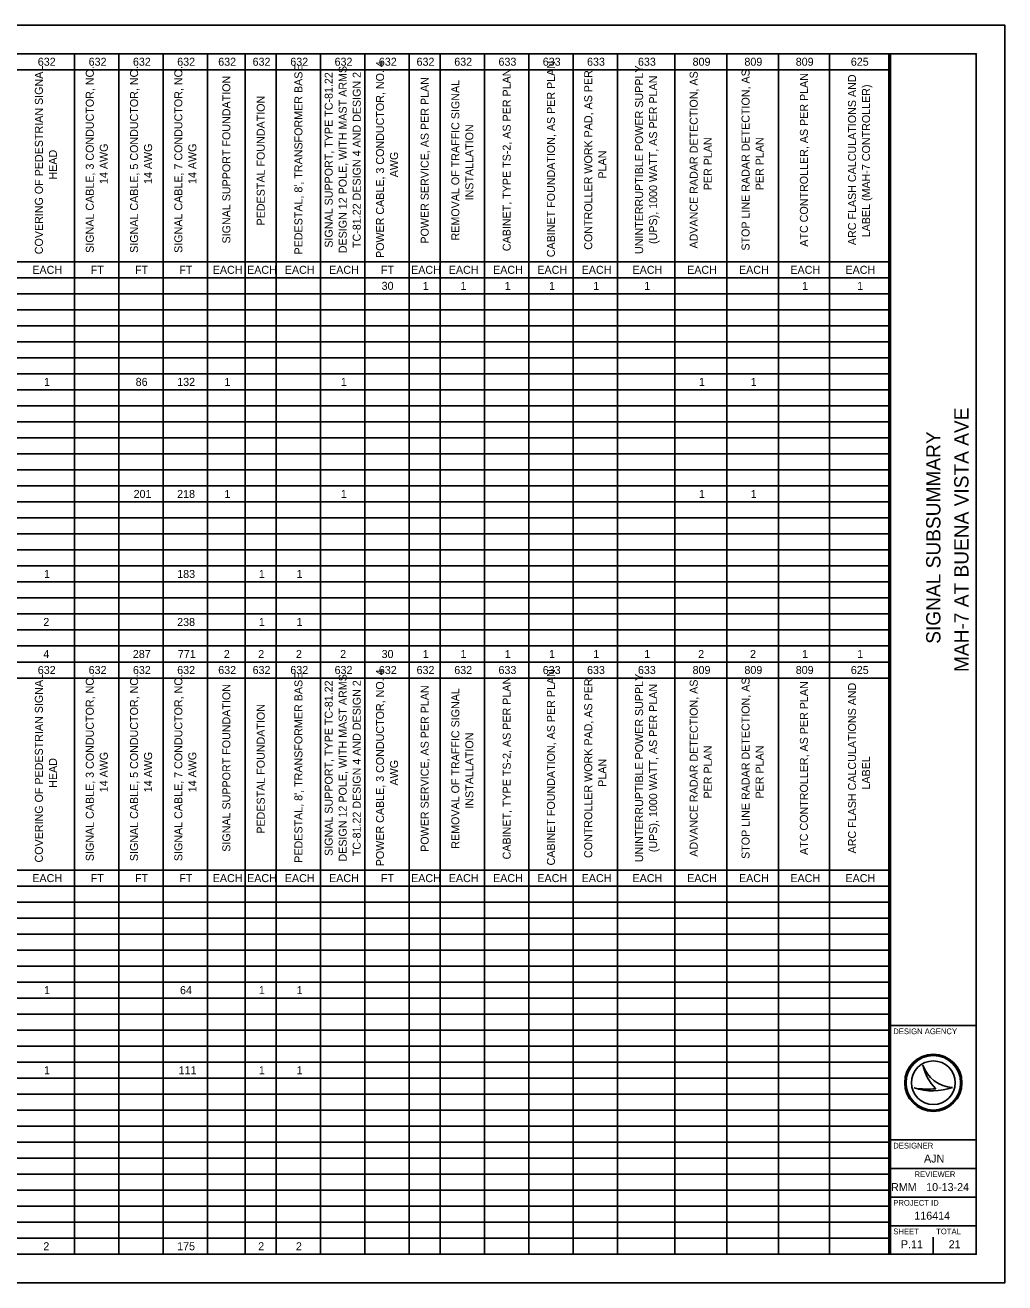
# Model space of a CAD drawing. Extents: x 0 to 34, y 0 to 22.
# Drawn here: x 16.88 to 34, y 0 to 22 of the extents above; entities that cross this region are included whole.
import ezdxf

# ---------------------------------------------------------------- set-up
doc = ezdxf.new("R2010")
doc.units = 0
for name, color, linetype in [('Default', 7, 'Continuous'), ('SH_Border', 7, 'Continuous'), ('SH_Cut_Line', 7, 'Continuous'), ('SH_Data', 7, 'Continuous'), ('SH_Text', 7, 'Continuous')]:
    doc.layers.add(name, color=color, linetype=linetype)

msp = doc.modelspace()

# ---------------------------------------------------------------- linework, layer by layer
at = {"layer": 'Default'}
for p, q in [((1.5, 21.5), (31.971, 21.5)), ((17.74, 21.5), (17.74, 10.86)), ((18.514, 21.5), (18.514, 10.86)), ((19.288, 21.5), (19.288, 10.86)), ((20.062, 21.5), (20.062, 10.86)), ((20.721, 21.5), (20.721, 10.86)), ((21.265, 21.5), (21.265, 10.86)), ((22.039, 21.5), (22.039, 10.86)), ((22.813, 21.5), (22.813, 10.86)), ((23.587, 21.5), (23.587, 10.86)), ((24.131, 21.5), (24.131, 10.86)), ((24.905, 21.5), (24.905, 10.86)), ((25.679, 21.5), (25.679, 10.86)), ((26.453, 21.5), (26.453, 10.86)), ((27.227, 21.5), (27.227, 10.86)), ((28.232, 21.5), (28.232, 10.86)), ((29.138, 21.5), (29.138, 10.86)), ((30.044, 21.5), (30.044, 10.86)), ((30.933, 21.5), (30.933, 10.86)), ((31.971, 21.5), (31.971, 10.86)), ((8.484, 21.22), (31.971, 21.22)), ((8.484, 17.86), (31.971, 17.86)), ((1.5, 17.58), (31.971, 17.58)), ((1.5, 17.3), (31.971, 17.3)), ((1.5, 17.02), (31.971, 17.02)), ((1.5, 16.74), (31.971, 16.74)), ((1.5, 16.46), (31.971, 16.46)), ((1.5, 16.18), (31.971, 16.18)), ((1.5, 15.9), (31.971, 15.9)), ((1.5, 15.62), (31.971, 15.62)), ((1.5, 15.34), (31.971, 15.34)), ((1.5, 15.06), (31.971, 15.06)), ((1.5, 14.78), (31.971, 14.78)), ((1.5, 14.5), (31.971, 14.5)), ((1.5, 14.22), (31.971, 14.22)), ((1.5, 13.94), (31.971, 13.94)), ((1.5, 13.66), (31.971, 13.66)), ((1.5, 13.38), (31.971, 13.38)), ((1.5, 13.1), (31.971, 13.1)), ((1.5, 12.82), (31.971, 12.82)), ((1.5, 12.54), (31.971, 12.54)), ((1.5, 12.26), (31.971, 12.26)), ((1.5, 11.98), (31.971, 11.98)), ((1.5, 11.7), (31.971, 11.7)), ((1.5, 11.42), (31.971, 11.42)), ((1.5, 11.14), (31.971, 11.14)), ((1.5, 10.86), (32.004, 10.86)), ((1.5, 10.86), (31.971, 10.86)), ((1.5, 10.86), (31.971, 10.86)), ((17.74, 10.86), (17.74, 0.5)), ((18.514, 10.86), (18.514, 0.5)), ((19.288, 10.86), (19.288, 0.5)), ((20.062, 10.86), (20.062, 0.5)), ((20.721, 10.86), (20.721, 0.5)), ((21.265, 10.86), (21.265, 0.5)), ((22.039, 10.86), (22.039, 0.5)), ((22.813, 10.86), (22.813, 0.5)), ((23.587, 10.86), (23.587, 0.5)), ((24.131, 10.86), (24.131, 0.5)), ((24.905, 10.86), (24.905, 0.5)), ((25.679, 10.86), (25.679, 0.5)), ((26.453, 10.86), (26.453, 0.5)), ((27.227, 10.86), (27.227, 0.5)), ((28.232, 10.86), (28.232, 0.5)), ((29.138, 10.86), (29.138, 0.5)), ((30.044, 10.86), (30.044, 0.5)), ((30.933, 10.86), (30.933, 0.5)), ((31.971, 10.86), (31.971, 0.5)), ((8.484, 10.58), (31.971, 10.58)), ((8.484, 7.22), (31.971, 7.22)), ((1.5, 6.94), (31.971, 6.94)), ((1.5, 6.66), (31.971, 6.66)), ((1.5, 6.38), (31.971, 6.38)), ((1.5, 6.1), (31.971, 6.1)), ((1.5, 5.82), (31.971, 5.82)), ((1.5, 5.54), (31.971, 5.54)), ((1.5, 5.26), (31.971, 5.26)), ((1.5, 4.98), (31.971, 4.98)), ((1.5, 4.7), (31.971, 4.7)), ((1.5, 4.42), (31.971, 4.42)), ((1.5, 4.14), (31.971, 4.14)), ((1.5, 3.86), (31.971, 3.86)), ((1.5, 3.58), (31.971, 3.58)), ((1.5, 3.3), (31.971, 3.3)), ((1.5, 3.02), (31.971, 3.02)), ((1.5, 2.74), (31.971, 2.74)), ((1.5, 2.46), (31.971, 2.46)), ((1.5, 2.18), (31.971, 2.18)), ((1.5, 1.9), (31.971, 1.9)), ((1.5, 1.62), (31.971, 1.62)), ((1.5, 1.34), (31.971, 1.34)), ((1.5, 1.06), (31.971, 1.06)), ((1.5, 0.78), (31.971, 0.78)), ((1.5, 0.5), (31.971, 0.5))]:
    msp.add_line(p, q, dxfattribs=at)
at = {"layer": 'SH_Border'}
for p, q in [((32, 0.5), (32, 21.5)), ((32, 4.5), (33.5, 4.5)), ((32, 2.5), (33.5, 2.5)), ((32, 2), (33.5, 2)), ((32, 1.5), (33.5, 1.5)), ((32, 1), (33.5, 1))]:
    msp.add_line(p, q, dxfattribs=at)
msp.add_lwpolyline([(1.5, 21.5), (33.5, 21.5), (33.5, 0.5), (1.5, 0.5)], close=True, dxfattribs=at)
at = {"layer": 'SH_Cut_Line'}
msp.add_lwpolyline([(0, 0), (34, 0), (34, 22), (0, 22)], close=True, dxfattribs=at)
at = {"layer": 'SH_Data'}
for p, q in [((32.567, 3.81), (32.567, 3.81)), ((32.417, 3.41), (32.417, 3.41)), ((32.75, 3.5), (32.75, 3.5)), ((33.087, 3.419), (33.087, 3.419)), ((32.375, 0.675), (32.375, 0.675)), ((32.75, 0.5), (32.75, 0.8))]:
    msp.add_line(p, q, dxfattribs=at)
for radius in [0.5, 0.477, 0.477, 0.382]:
    msp.add_circle((32.75, 3.5), radius, dxfattribs=at)
for centre, radius, start, end in [((33.116, 3.998), 0.58, 198.9257, 198.9319), ((33.347, 3.97), 0.796, 191.6379, 191.6421), ((33.116, 3.998), 0.58, 198.9319, 267.1657), ((33.347, 3.97), 0.796, 191.6421, 226.0947), ((32.739, 4.37), 1.013, 251.4576, 290.0832), ((32.648, 4.654), 1.266, 259.4964, 259.4995), ((32.739, 4.37), 1.013, 251.4527, 251.4576), ((32.648, 4.654), 1.266, 259.4995, 276.6672)]:
    msp.add_arc(centre, radius, start, end, dxfattribs=at)

# ---------------------------------------------------------------- texts
at = {"layer": 'Default'}
for s, p in [('632', (17.096, 21.29)), ('632', (17.985, 21.29)), ('632', (18.759, 21.29)), ('632', (19.533, 21.29)), ('632', (20.25, 21.29)), ('632', (20.851, 21.29)), ('632', (21.51, 21.29)), ('632', (22.284, 21.29)), ('632', (23.058, 21.29)), ('632', (23.717, 21.29)), ('632', (24.376, 21.29)), ('633', (25.149, 21.29)), ('633', (25.923, 21.29)), ('633', (26.697, 21.29)), ('633', (27.587, 21.29)), ('809', (28.542, 21.29)), ('809', (29.448, 21.29)), ('809', (30.345, 21.29)), ('625', (31.308, 21.29)), ('EACH', (17, 17.65)), ('FT', (18.021, 17.65)), ('FT', (18.795, 17.65)), ('FT', (19.57, 17.65)), ('EACH', (20.154, 17.65)), ('EACH', (20.755, 17.65)), ('EACH', (21.414, 17.65)), ('EACH', (22.188, 17.65)), ('FT', (23.094, 17.65)), ('EACH', (23.621, 17.65)), ('EACH', (24.28, 17.65)), ('EACH', (25.054, 17.65)), ('EACH', (25.828, 17.65)), ('EACH', (26.603, 17.65)), ('EACH', (27.492, 17.65)), ('EACH', (28.447, 17.65)), ('EACH', (29.353, 17.65)), ('EACH', (30.251, 17.65)), ('EACH', (31.214, 17.65)), ('30', (23.106, 17.37)), ('1', (23.826, 17.37)), ('1', (24.485, 17.37)), ('1', (25.259, 17.37)), ('1', (26.033, 17.37)), ('1', (26.807, 17.37)), ('1', (27.697, 17.37)), ('1', (30.456, 17.37)), ('1', (31.419, 17.37)), ('1', (17.205, 15.69)), ('86', (18.807, 15.69)), ('132', (19.533, 15.69)), ('1', (20.359, 15.69)), ('1', (22.393, 15.69)), ('1', (28.652, 15.69)), ('1', (29.558, 15.69)), ('201', (18.771, 13.73)), ('218', (19.532, 13.73)), ('1', (20.359, 13.73)), ('1', (22.393, 13.73)), ('1', (28.652, 13.73)), ('1', (29.558, 13.73)), ('1', (17.205, 12.33)), ('183', (19.533, 12.33)), ('1', (20.96, 12.33)), ('1', (21.619, 12.33)), ('2', (17.193, 11.49)), ('238', (19.532, 11.49)), ('1', (20.96, 11.49)), ('1', (21.619, 11.49)), ('4', (17.193, 10.93)), ('287', (18.758, 10.93)), ('771', (19.545, 10.93)), ('2', (20.348, 10.93)), ('2', (20.949, 10.93)), ('2', (21.608, 10.93)), ('2', (22.382, 10.93)), ('30', (23.106, 10.93)), ('1', (23.826, 10.93)), ('1', (24.485, 10.93)), ('1', (25.259, 10.93)), ('1', (26.033, 10.93)), ('1', (26.807, 10.93)), ('1', (27.697, 10.93)), ('2', (28.64, 10.93)), ('2', (29.546, 10.93)), ('1', (30.456, 10.93)), ('1', (31.419, 10.93)), ('632', (17.096, 10.65)), ('632', (17.985, 10.65)), ('632', (18.759, 10.65)), ('632', (19.533, 10.65)), ('632', (20.25, 10.65)), ('632', (20.851, 10.65)), ('632', (21.51, 10.65)), ('632', (22.284, 10.65)), ('632', (23.058, 10.65)), ('632', (23.717, 10.65)), ('632', (24.376, 10.65)), ('633', (25.149, 10.65)), ('633', (25.923, 10.65)), ('633', (26.697, 10.65)), ('633', (27.587, 10.65)), ('809', (28.542, 10.65)), ('809', (29.448, 10.65)), ('809', (30.345, 10.65)), ('625', (31.308, 10.65)), ('EACH', (17, 7.01)), ('FT', (18.021, 7.01)), ('FT', (18.795, 7.01)), ('FT', (19.57, 7.01)), ('EACH', (20.154, 7.01)), ('EACH', (20.755, 7.01)), ('EACH', (21.414, 7.01)), ('EACH', (22.188, 7.01)), ('FT', (23.094, 7.01)), ('EACH', (23.621, 7.01)), ('EACH', (24.28, 7.01)), ('EACH', (25.054, 7.01)), ('EACH', (25.828, 7.01)), ('EACH', (26.603, 7.01)), ('EACH', (27.492, 7.01)), ('EACH', (28.447, 7.01)), ('EACH', (29.353, 7.01)), ('EACH', (30.251, 7.01)), ('EACH', (31.214, 7.01)), ('1', (17.205, 5.05)), ('64', (19.582, 5.05)), ('1', (20.96, 5.05)), ('1', (21.619, 5.05)), ('1', (17.205, 3.65)), ('111', (19.558, 3.65)), ('1', (20.96, 3.65)), ('1', (21.619, 3.65)), ('2', (17.193, 0.57)), ('175', (19.532, 0.57)), ('2', (20.949, 0.57)), ('2', (21.608, 0.57))]:
    msp.add_text(s, height=0.14, dxfattribs=at).set_placement(p)
for s, p in [('POWER CABLE, 3 CONDUCTOR, NO. 4 ', (23.148, 17.927)), ('CABINET FOUNDATION, AS PER PLAN', (26.136, 17.941)), ('COVERING OF PEDESTRIAN SIGNAL ', (17.185, 17.993)), ('SIGNAL CABLE, 3 CONDUCTOR, NO. ', (18.075, 18.017)), ('SIGNAL CABLE, 5 CONDUCTOR, NO. ', (18.849, 18.017)), ('SIGNAL CABLE, 7 CONDUCTOR, NO. ', (19.623, 18.017)), ("PEDESTAL, 8', TRANSFORMER BASE", (21.722, 17.989)), ('SIGNAL SUPPORT, TYPE TC-81.22 ', (22.251, 18.108)), ('DESIGN 12 POLE, WITH MAST ARMS ', (22.496, 18.01)), ('TC-81.22 DESIGN 4 AND DESIGN 2', (22.741, 18.102)), ('CABINET, TYPE TS-2, AS PER PLAN', (25.362, 18.047)), ('CONTROLLER WORK PAD, AS PER ', (26.788, 18.071)), ('UNINTERRUPTIBLE POWER SUPPLY ', (27.677, 17.997)), ('ADVANCE RADAR DETECTION, AS ', (28.632, 18.093)), ('STOP LINE RADAR DETECTION, AS ', (29.538, 18.056)), ('ATC CONTROLLER, AS PER PLAN', (30.558, 18.125)), ('ARC FLASH CALCULATIONS AND ', (31.399, 18.152)), ('SIGNAL SUPPORT FOUNDATION', (20.462, 18.181)), ('POWER SERVICE, AS PER PLAN', (23.929, 18.179)), ('REMOVAL OF TRAFFIC SIGNAL ', (24.465, 18.234)), ('(UPS), 1000 WATT, AS PER PLAN', (27.922, 18.173)), ('LABEL (MAH-7 CONTROLLER)', (31.644, 18.289)), ('PEDESTAL FOUNDATION', (21.063, 18.497)), ('INSTALLATION', (24.71, 18.934)), ('PER PLAN', (28.877, 19.112)), ('PER PLAN', (29.783, 19.112)), ('HEAD', (17.43, 19.3)), ('14 AWG', (18.32, 19.221)), ('14 AWG', (19.094, 19.221)), ('14 AWG', (19.868, 19.221)), ('AWG', (23.393, 19.339)), ('PLAN', (27.033, 19.317)), ('COVERING OF PEDESTRIAN SIGNAL ', (17.185, 7.353)), ('SIGNAL CABLE, 3 CONDUCTOR, NO. ', (18.075, 7.377)), ('SIGNAL CABLE, 5 CONDUCTOR, NO. ', (18.849, 7.377)), ('SIGNAL CABLE, 7 CONDUCTOR, NO. ', (19.623, 7.377)), ("PEDESTAL, 8', TRANSFORMER BASE", (21.722, 7.349)), ('DESIGN 12 POLE, WITH MAST ARMS ', (22.496, 7.37)), ('POWER CABLE, 3 CONDUCTOR, NO. 4 ', (23.148, 7.287)), ('CABINET, TYPE TS-2, AS PER PLAN', (25.362, 7.407)), ('CABINET FOUNDATION, AS PER PLAN', (26.136, 7.301)), ('CONTROLLER WORK PAD, AS PER ', (26.788, 7.431)), ('UNINTERRUPTIBLE POWER SUPPLY ', (27.677, 7.357)), ('STOP LINE RADAR DETECTION, AS ', (29.538, 7.416)), ('SIGNAL SUPPORT FOUNDATION', (20.462, 7.541)), ('SIGNAL SUPPORT, TYPE TC-81.22 ', (22.251, 7.468)), ('TC-81.22 DESIGN 4 AND DESIGN 2', (22.741, 7.462)), ('POWER SERVICE, AS PER PLAN', (23.929, 7.539)), ('REMOVAL OF TRAFFIC SIGNAL ', (24.465, 7.594)), ('(UPS), 1000 WATT, AS PER PLAN', (27.922, 7.533)), ('ADVANCE RADAR DETECTION, AS ', (28.632, 7.453)), ('ATC CONTROLLER, AS PER PLAN', (30.558, 7.485)), ('ARC FLASH CALCULATIONS AND ', (31.399, 7.512)), ('PEDESTAL FOUNDATION', (21.063, 7.857)), ('INSTALLATION', (24.71, 8.294)), ('14 AWG', (18.32, 8.581)), ('14 AWG', (19.094, 8.581)), ('14 AWG', (19.868, 8.581)), ('PER PLAN', (28.877, 8.472)), ('PER PLAN', (29.783, 8.472)), ('HEAD', (17.43, 8.66)), ('AWG', (23.393, 8.699)), ('PLAN', (27.033, 8.677)), ('LABEL', (31.644, 8.629))]:
    msp.add_text(s, height=0.14, rotation=90, dxfattribs=at).set_placement(p)
at = {"layer": 'SH_Data'}
msp.add_text('SIGNAL SUBSUMMARY', height=0.25, rotation=90, dxfattribs=at).set_placement((32.875, 11.179))
for s, height, p in [('DESIGN AGENCY', 0.1, (32.05, 4.35)), ('DESIGNER', 0.1, (32.05, 2.35)), ('AJN', 0.14, (32.588, 2.105)), ('REVIEWER', 0.1, (32.422, 1.85)), ('RMM', 0.14, (32.011, 1.605)), ('10-13-24', 0.14, (32.625, 1.605)), ('PROJECT ID', 0.1, (32.05, 1.35)), ('116414', 0.14, (32.418, 1.105)), ('SHEET', 0.1, (32.05, 0.85)), ('TOTAL', 0.1, (32.8, 0.85)), ('P.11', 0.14, (32.184, 0.605)), ('21', 0.14, (33.019, 0.605))]:
    msp.add_text(s, height=height, dxfattribs=at).set_placement(p)
at = {"layer": 'SH_Text'}
msp.add_text('MAH-7 AT BUENA VISTA AVE', height=0.25, rotation=90, dxfattribs=at).set_placement((33.365, 10.685))

doc.saveas('drawing.dxf')
